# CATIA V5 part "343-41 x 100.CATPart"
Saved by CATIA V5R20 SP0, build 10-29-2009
Part number: 343-41 x 100
Definition: NONE
Nomenclature: 343-41 x 100
Source: Unknown
Description: 343-41 x 100
Bounding box of the stored display mesh (mm): x 0 to 100, y -27.5 to 27.5, z -27.5 to 27.5
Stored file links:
  C:\Users\Utente\Desktop\IO LAVORO\3D X SITO CF\X SITO\343-348\343-41 x 100.CATPart
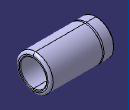
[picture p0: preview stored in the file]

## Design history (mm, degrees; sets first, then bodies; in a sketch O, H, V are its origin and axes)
Body1 "343-41 x 100" (main body)
  Solid1: solid without history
